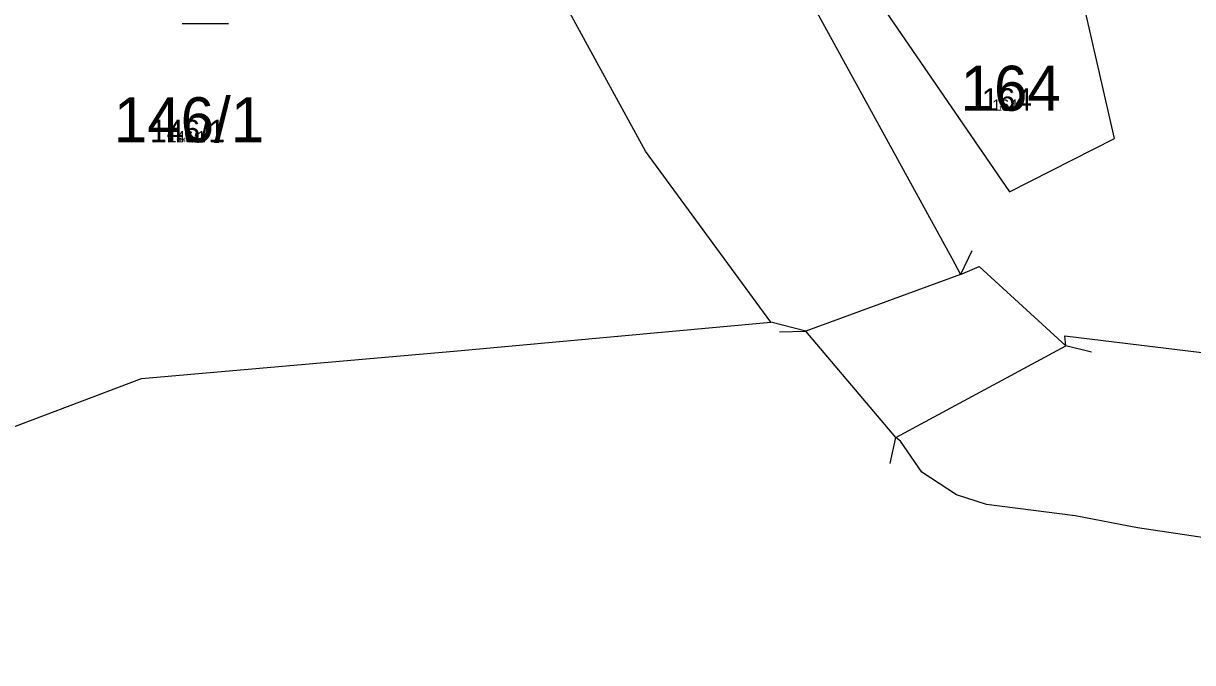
# Model space of a CAD drawing. Extents: x -744652 to -739090, y -980828 to -975855.
# Drawn here: x -742427.42 to -742383.22, y -978744.26 to -978720.11 of the extents above; entities that cross this region are included whole.
import ezdxf

# ---------------------------------------------------------------- set-up
doc = ezdxf.new("R2010")
doc.units = 0
for name, color, linetype in [('KAT_02_hranice parcel', 7, 'Continuous'), ('KAT_03_1000_čísla parcelní', 7, 'Continuous'), ('KAT_03_100_čísla parcelní', 7, 'Continuous'), ('KAT_03_250_čísla parcelní', 7, 'Continuous'), ('KAT_03_500_čísla parcelní', 7, 'Continuous'), ('KAT_04_vnitřní kresba', 7, 'Continuous'), ('KAT_05_1000_značky kultur', 7, 'Continuous'), ('KAT_05_100_značky kultur', 7, 'Continuous'), ('KAT_05_250_značky kultur', 7, 'Continuous'), ('KAT_05_500_značky kultur', 7, 'Continuous')]:
    doc.layers.add(name, color=color, linetype=linetype)

msp = doc.modelspace()

# ---------------------------------------------------------------- linework, layer by layer
at = {"layer": 'KAT_02_hranice parcel'}
for points in [[(-742399.17, -978731.4), (-742403.9, -978724.94), (-742411.95, -978710.22), (-742415.01, -978708), (-742425.62, -978706.57), (-742447.98, -978705.87)], [(-742404.92, -978706.02), (-742392.32, -978728.98), (-742392, -978729.6), (-742391.29, -978729.29), (-742388.01, -978732.29), (-742388.05, -978731.92), (-742366.82, -978734.5), (-742362.9, -978735.46), (-742361.94, -978735.42), (-742361.36, -978735.86), (-742361.25, -978735.7), (-742356.93, -978739.76), (-742357.22, -978740.16), (-742351.74, -978744.05)], [(-742395.27, -978718.99), (-742390.14, -978726.48), (-742386.17, -978724.46), (-742387.78, -978717.4)], [(-742435.92, -978738.43), (-742422.96, -978733.52), (-742411.01, -978732.48), (-742399.17, -978731.4)], [(-742330.54, -978774), (-742334.39, -978771.9), (-742345.32, -978763.82), (-742349.74, -978758.28), (-742354.1, -978752.58), (-742357.7, -978749.22), (-742362.74, -978745.15), (-742365.99, -978743.11), (-742367.63, -978742.38), (-742369.86, -978741.8), (-742374.48, -978740.78), (-742385.3, -978739.17), (-742387.66, -978738.72), (-742391.01, -978738.29), (-742392.15, -978737.92), (-742393.45, -978737.07), (-742394.26, -978735.9), (-742394.44, -978735.76), (-742397.84, -978731.74), (-742399.17, -978731.4)]]:
    msp.add_lwpolyline(points, dxfattribs=at)
at = {"layer": 'KAT_04_vnitřní kresba'}
for p, q in [((-742391.561, -978728.701), (-742391.999, -978729.6)), ((-742392, -978729.6), (-742397.84, -978731.74)), ((-742398.84, -978731.757), (-742397.841, -978731.739)), ((-742394.44, -978735.76), (-742388.01, -978732.29)), ((-742387.039, -978732.533), (-742388.01, -978732.291)), ((-742394.649, -978736.738), (-742394.441, -978735.76))]:
    msp.add_line(p, q, dxfattribs=at)
at = {"layer": 'KAT_05_1000_značky kultur'}
msp.add_line((-742421.413, -978720.11), (-742419.663, -978720.11), dxfattribs=at)
at = {"layer": 'KAT_05_100_značky kultur'}
msp.add_line((-742421.419, -978720.11), (-742421.244, -978720.11), dxfattribs=at)
at = {"layer": 'KAT_05_250_značky kultur'}
msp.add_line((-742421.418, -978720.11), (-742420.981, -978720.11), dxfattribs=at)
at = {"layer": 'KAT_05_500_značky kultur'}
msp.add_line((-742421.417, -978720.11), (-742420.542, -978720.11), dxfattribs=at)

# ---------------------------------------------------------------- texts
at = {"layer": 'KAT_03_1000_čísla parcelní'}
for s, p in [('164', (-742391.994, -978723.41)), ('146/1', (-742424.003, -978724.6))]:
    msp.add_text(s, height=1.7, dxfattribs=at).set_placement(p)
at = {"layer": 'KAT_03_100_čísla parcelní'}
for s, p in [('164', (-742390.549, -978723.41)), ('146/1', (-742421.54, -978724.6))]:
    msp.add_text(s, height=0.17, dxfattribs=at).set_placement(p)
at = {"layer": 'KAT_03_250_čísla parcelní'}
for s, p in [('164', (-742390.789, -978723.41)), ('146/1', (-742421.95, -978724.6))]:
    msp.add_text(s, height=0.425, dxfattribs=at).set_placement(p)
at = {"layer": 'KAT_03_500_čísla parcelní'}
for s, p in [('164', (-742391.191, -978723.41)), ('146/1', (-742422.634, -978724.6))]:
    msp.add_text(s, height=0.85, dxfattribs=at).set_placement(p)

doc.saveas('drawing.dxf')
